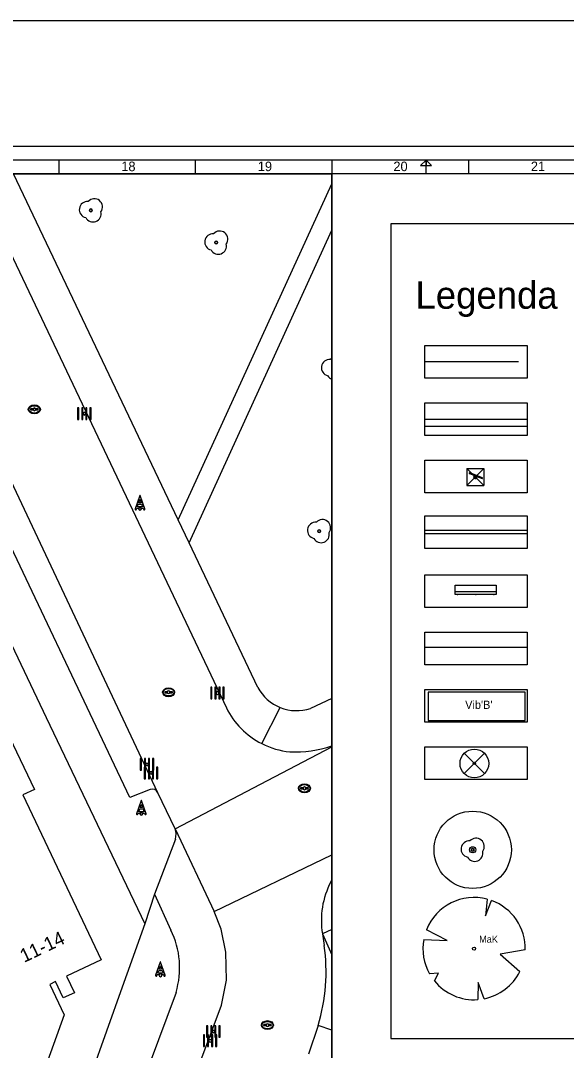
# Model space of a CAD drawing. Extents: x 192664 to 192925, y 446334 to 446521.
# Drawn here: x 192837.8 to 192877.8, y 446445.5 to 446521 of the extents above; entities that cross this region are included whole.
import ezdxf

# ---------------------------------------------------------------- set-up
doc = ezdxf.new("R2010")
doc.units = 0
for name, color, linetype in [('( Toegevoegd 29-11-2021 14_41_42) wegdeel vlak', 7, 'Continuous'), ('1010 viewport', 7, 'Continuous'), ('201011 legenda', 7, 'Continuous'), ('201020 hulplijnen', 7, 'Continuous'), ('205134 wortelgeleidingsscherm', 7, 'Continuous'), ('B-GV-GR-BOOM-S', 7, 'Continuous'), ('B-GV-KG-GRENS_WERKGRENS-G', 7, 'Continuous'), ('boom', 7, 'Continuous'), ('bovenleidingmast', 7, 'Continuous'), ('huisnummerreeks BGT', 7, 'Continuous'), ('inspectie-   rioolput', 7, 'Continuous'), ('kant open verharding', 7, 'Continuous'), ('kant verharding', 7, 'Continuous'), ('kolk', 7, 'Continuous'), ('N-GV-GR-BEPLANTING-G', 7, 'Continuous'), ('N-GV-GR-BOOM-S', 7, 'Continuous'), ('N-GV-IE-MEUBILAIR_WEGMEUBILAIR_ZITBANK-S', 7, 'Continuous'), ('N-GV-VH-VERHARDING_HALFVERHARDING-G', 7, 'Continuous'), ('pand op maaiveld vlak', 7, 'Continuous'), ('speelvoorziening', 7, 'Continuous'), ('TEKST', 7, 'Continuous'), ('V-GV-IE-MEUBILAIR_WEGMEUBILAIR_SPEELTOESTEL-G', 7, 'Continuous'), ('verkeerseiland - berm', 7, 'Continuous'), ('X-XX-AL-TEKENBLAD-S', 7, 'Continuous'), ('X-XX-AL-TEKENBLAD_KADER-G', 7, 'Continuous')]:
    doc.layers.add(name, color=color, linetype=linetype)

msp = doc.modelspace()

# ---------------------------------------------------------------- linework, layer by layer
at = {"layer": '( Toegevoegd 29-11-2021 14_41_42) wegdeel vlak'}
for p, q in [((192849.384, 446484.404), (192860.643, 446509.019)), ((192850.183, 446482.725), (192860.643, 446505.623)), ((192867.462, 446491.779), (192874.962, 446491.779))]:
    msp.add_line(p, q, dxfattribs=at)
at = {"layer": '1010 viewport'}
msp.add_lwpolyline([(192675.743, 446509.756), (192860.643, 446509.756), (192860.643, 446345.556), (192675.743, 446345.556)], close=True, dxfattribs=at)
at = {"layer": '201011 legenda'}
msp.add_line((192860.643, 446345.556), (192860.643, 446509.756), dxfattribs=at)
for points in [[(192867.462, 446497.179), (192874.962, 446497.179), (192874.962, 446494.779), (192867.462, 446494.779)], [(192867.462, 446492.979), (192874.962, 446492.979), (192874.962, 446490.579), (192867.462, 446490.579)], [(192867.462, 446488.779), (192874.962, 446488.779), (192874.962, 446486.379), (192867.462, 446486.379)], [(192867.462, 446484.702), (192874.962, 446484.702), (192874.962, 446482.302), (192867.462, 446482.302)], [(192867.462, 446480.379), (192874.962, 446480.379), (192874.962, 446477.979), (192867.462, 446477.979)], [(192867.462, 446476.179), (192874.962, 446476.179), (192874.962, 446473.779), (192867.462, 446473.779)], [(192867.462, 446471.979), (192874.962, 446471.979), (192874.962, 446469.579), (192867.462, 446469.579)], [(192867.462, 446467.779), (192874.962, 446467.779), (192874.962, 446465.379), (192867.462, 446465.379)]]:
    msp.add_lwpolyline(points, close=True, dxfattribs=at)
at = {"layer": '201020 hulplijnen'}
msp.add_lwpolyline([(192864.958, 446446.417), (192902.755, 446446.417), (192902.755, 446506.094), (192864.958, 446506.094)], close=True, dxfattribs=at)
at = {"layer": '205134 wortelgeleidingsscherm'}
msp.add_line((192867.462, 446475.064), (192874.962, 446475.064), dxfattribs=at)
at = {"layer": 'B-GV-GR-BOOM-S'}
for p, q in [((192871.852, 446467.325), (192870.317, 446465.79)), ((192871.852, 446465.79), (192870.317, 446467.325))]:
    msp.add_line(p, q, dxfattribs=at)
for centre, radius in [((192871.085, 446466.557), 1.05), ((192871.085, 446466.557), 0.084), ((192870.961, 446460.232), 2.832), ((192870.961, 446460.232), 0.227)]:
    msp.add_circle(centre, radius, dxfattribs=at)
at = {"layer": 'B-GV-KG-GRENS_WERKGRENS-G'}
msp.add_line((192874.314, 446495.979), (192867.462, 446495.979), dxfattribs=at)
at = {"layer": 'boom'}
for p, q in [((192860.643, 446495.55), (192860.643, 446496.247)), ((192860.643, 446495.45), (192860.643, 446495.55)), ((192860.643, 446494.699), (192860.643, 446495.45))]:
    msp.add_line(p, q, dxfattribs=at)
for centre in [(192842.997, 446507.076), (192852.18, 446504.71), (192859.71, 446483.574), (192870.961, 446460.232)]:
    msp.add_circle(centre, 0.1, dxfattribs=at)
for centre, radius, start, end in [((192842.747, 446507.126), 0.6, 85.13702, 257.75442), ((192843.247, 446507.326), 0.6, 323.54458, 138.4658), ((192843.147, 446506.826), 0.6, 208.50578, 13.83556), ((192842.997, 446507.076), 0.1, 0, 180), ((192842.997, 446507.076), 0.1, 180, 0), ((192851.93, 446504.76), 0.6, 85.13702, 257.75442), ((192852.43, 446504.96), 0.6, 323.54458, 138.4658), ((192852.33, 446504.46), 0.6, 208.50578, 13.83556), ((192852.18, 446504.71), 0.1, 0, 180), ((192852.18, 446504.71), 0.1, 180, 0), ((192860.48, 446495.55), 0.6, 85.13702, 257.75442), ((192860.98, 446495.75), 0.6, 124.12747, 138.4658), ((192860.73, 446495.5), 0.1, 150.02178, 209.97822), ((192860.73, 446495.5), 0.1, 150.02178, 209.97822), ((192860.88, 446495.25), 0.6, 208.50578, 246.77336), ((192859.46, 446483.624), 0.6, 85.13702, 257.75442), ((192859.96, 446483.824), 0.6, 323.54458, 138.4658), ((192859.86, 446483.324), 0.6, 208.50578, 13.83556), ((192859.71, 446483.574), 0.1, 0, 180), ((192859.71, 446483.574), 0.1, 180, 0), ((192870.711, 446460.282), 0.6, 85.13702, 257.75442), ((192871.211, 446460.482), 0.6, 323.54458, 138.4658), ((192871.111, 446459.982), 0.6, 208.50578, 13.83556), ((192870.961, 446460.232), 0.1, 0, 180), ((192870.961, 446460.232), 0.1, 180, 0)]:
    msp.add_arc(centre, radius, start, end, dxfattribs=at)
at = {"layer": 'bovenleidingmast'}
for p, q in [((192846.583, 446486.18), (192846.242, 446485.207)), ((192846.942, 446485.207), (192846.601, 446486.18)), ((192846.684, 446463.846), (192846.343, 446462.873)), ((192847.043, 446462.873), (192846.702, 446463.846)), ((192848.079, 446452.011), (192847.738, 446451.038)), ((192848.438, 446451.038), (192848.097, 446452.011))]:
    msp.add_line(p, q, dxfattribs=at)
for points in [[(192846.714, 446485.557), (192846.784, 446485.357), (192846.4, 446485.357), (192846.47, 446485.557)], [(192846.815, 446463.223), (192846.885, 446463.023), (192846.501, 446463.023), (192846.571, 446463.223)], [(192848.21, 446451.388), (192848.28, 446451.188), (192847.896, 446451.188), (192847.966, 446451.388)]]:
    msp.add_lwpolyline(points, close=True, dxfattribs=at)
for points in [[(192846.601, 446485.877), (192846.679, 446485.657), (192846.505, 446485.657), (192846.583, 446485.877)], [(192846.336, 446485.174), (192846.365, 446485.257), (192846.505, 446485.257)], [(192846.679, 446485.257), (192846.819, 446485.257), (192846.848, 446485.174)], [(192846.702, 446463.543), (192846.78, 446463.323), (192846.606, 446463.323), (192846.684, 446463.543)], [(192846.437, 446462.84), (192846.466, 446462.923), (192846.606, 446462.923)], [(192846.78, 446462.923), (192846.92, 446462.923), (192846.949, 446462.84)], [(192848.097, 446451.708), (192848.175, 446451.488), (192848.001, 446451.488), (192848.079, 446451.708)], [(192847.832, 446451.005), (192847.861, 446451.088), (192848.001, 446451.088)], [(192848.175, 446451.088), (192848.315, 446451.088), (192848.344, 446451.005)]]:
    msp.add_lwpolyline(points, dxfattribs=at)
for centre, radius, start, end in [((192846.592, 446486.177), 0.01, 19.29005, 160.70995), ((192846.592, 446485.874), 0.01, 19.29005, 160.70995), ((192846.289, 446485.19), 0.05, 160.70995, 340.70995), ((192846.592, 446485.207), 0.1, 0, 180), ((192846.592, 446485.207), 0.1, 180, 0), ((192846.592, 446485.207), 0.1, 30, 150), ((192846.895, 446485.19), 0.05, 199.29005, 19.29005), ((192846.693, 446463.843), 0.01, 19.29005, 160.70995), ((192846.693, 446463.54), 0.01, 19.29005, 160.70995), ((192846.39, 446462.856), 0.05, 160.70995, 340.70995), ((192846.693, 446462.873), 0.1, 0, 180), ((192846.693, 446462.873), 0.1, 180, 0), ((192846.693, 446462.873), 0.1, 30, 150), ((192846.996, 446462.856), 0.05, 199.29005, 19.29005), ((192848.088, 446452.008), 0.01, 19.29005, 160.70995), ((192848.088, 446451.705), 0.01, 19.29005, 160.70995), ((192847.785, 446451.021), 0.05, 160.70995, 340.70995), ((192848.088, 446451.038), 0.1, 0, 180), ((192848.088, 446451.038), 0.1, 180, 0), ((192848.088, 446451.038), 0.1, 30, 150), ((192848.391, 446451.021), 0.05, 199.29005, 19.29005)]:
    msp.add_arc(centre, radius, start, end, dxfattribs=at)
at = {"layer": 'inspectie-   rioolput'}
for p, q in [((192838.76, 446492.534), (192838.603, 446492.534)), ((192838.603, 446492.459), (192838.76, 446492.459)), ((192839.103, 446492.534), (192838.946, 446492.534)), ((192838.946, 446492.459), (192839.103, 446492.459)), ((192848.596, 446471.812), (192848.439, 446471.812)), ((192848.939, 446471.812), (192848.782, 446471.812)), ((192848.439, 446471.737), (192848.596, 446471.737)), ((192848.782, 446471.737), (192848.939, 446471.737)), ((192858.543, 446464.774), (192858.386, 446464.774)), ((192858.386, 446464.699), (192858.543, 446464.699)), ((192858.886, 446464.774), (192858.729, 446464.774)), ((192858.729, 446464.699), (192858.886, 446464.699)), ((192855.834, 446447.427), (192855.677, 446447.427)), ((192855.677, 446447.353), (192855.834, 446447.353)), ((192856.177, 446447.427), (192856.02, 446447.427)), ((192856.02, 446447.353), (192856.177, 446447.353))]:
    msp.add_line(p, q, dxfattribs=at)
for centre, radius, start, end in [((192838.603, 446492.496), 0.0375, 90, 270), ((192838.853, 446492.496), 0.1, 0, 180), ((192838.853, 446492.496), 0.1, 157.97569, 180), ((192838.853, 446492.496), 0.1, 180, 202.02431), ((192838.853, 446492.496), 0.1, 180, 0), ((192838.853, 446492.496), 0.1, 0, 22.02431), ((192838.853, 446492.496), 0.1, 337.97569, 0), ((192839.103, 446492.496), 0.0375, 270, 90), ((192848.439, 446471.775), 0.0375, 90, 270), ((192848.689, 446471.775), 0.1, 0, 180), ((192848.689, 446471.775), 0.1, 157.97569, 180), ((192848.689, 446471.775), 0.1, 180, 202.02431), ((192848.689, 446471.775), 0.1, 180, 0), ((192848.689, 446471.775), 0.1, 0, 22.02431), ((192848.689, 446471.775), 0.1, 337.97569, 0), ((192848.939, 446471.775), 0.0375, 270, 90), ((192858.386, 446464.737), 0.0375, 90, 270), ((192858.636, 446464.737), 0.1, 0, 180), ((192858.636, 446464.737), 0.1, 157.97569, 180), ((192858.636, 446464.737), 0.1, 180, 202.02431), ((192858.636, 446464.737), 0.1, 180, 0), ((192858.636, 446464.737), 0.1, 0, 22.02431), ((192858.636, 446464.737), 0.1, 337.97569, 0), ((192858.886, 446464.737), 0.0375, 270, 90), ((192855.677, 446447.39), 0.0375, 90, 270), ((192855.927, 446447.39), 0.1, 0, 180), ((192855.927, 446447.39), 0.1, 157.97569, 180), ((192855.927, 446447.39), 0.1, 180, 202.02431), ((192855.927, 446447.39), 0.1, 180, 0), ((192855.927, 446447.39), 0.1, 0, 22.02431), ((192855.927, 446447.39), 0.1, 337.97569, 0), ((192856.177, 446447.39), 0.0375, 270, 90)]:
    msp.add_arc(centre, radius, start, end, dxfattribs=at)
for centre, major_axis, ratio in [((192838.853, 446492.496), (-0.442, 0), 0.73911), ((192838.853, 446492.496), (-0.392, 0), 0.689655), ((192848.689, 446471.775), (-0.442, 0), 0.73911), ((192848.689, 446471.775), (-0.392, 0), 0.689655), ((192858.636, 446464.737), (-0.442, 0), 0.73911), ((192858.636, 446464.737), (-0.392, 0), 0.689655), ((192855.927, 446447.39), (-0.442, 0), 0.73911), ((192855.927, 446447.39), (-0.392, 0), 0.689655)]:
    msp.add_ellipse(centre, major_axis=major_axis, ratio=ratio, dxfattribs=at)
at = {"layer": 'kant open verharding'}
for p, q in [((192849.384, 446484.404), (192837.327, 446509.756)), ((192835.606, 446507.086), (192852.92, 446470.626)), ((192850.183, 446482.725), (192849.384, 446484.404)), ((192855.223, 446472.129), (192850.183, 446482.725)), ((192860.643, 446471.328), (192859.082, 446470.584)), ((192855.509, 446468.01), (192856.872, 446470.656)), ((192849.159, 446461.777), (192860.643, 446467.769)), ((192849.159, 446461.777), (192847.908, 446464.417)), ((192852.016, 446455.709), (192860.643, 446459.852)), ((192847.645, 446456.987), (192846.946, 446454.816)), ((192860.643, 446454.394), (192859.957, 446454.068)), ((192859.639, 446447.374), (192858.944, 446445.253))]:
    msp.add_line(p, q, dxfattribs=at)
for points in [[(192820.967, 446509.756), (192830.801, 446488.882), (192835.291, 446479.169), (192839.711, 446469.931), (192846.946, 446454.816)], [(192846.946, 446454.816), (192845.635, 446451.129), (192845.293, 446450.169), (192841.851, 446440.492), (192835.693, 446423.446), (192835.401, 446422.35)]]:
    msp.add_lwpolyline(points, dxfattribs=at)
for centre, radius, start, end in [((192858.074, 446473.662), 3.237, 208.25805, 248.19512), ((192858.147, 446473.21), 5.83, 206.30393, 243.10165), ((192858.076, 446473.668), 3.244, 248.20975, 288.05827), ((192858.148, 446473.204), 5.826, 243.06402, 264.2745), ((192857.92, 446475.928), 8.528, 267.62464, 288.62029)]:
    msp.add_arc(centre, radius, start, end, dxfattribs=at)
at = {"layer": 'kant verharding'}
for p, q in [((192847.908, 446464.417), (192829.185, 446504.028)), ((192849.159, 446461.777), (192852.016, 446455.709)), ((192849.185, 446461.016), (192847.645, 446456.987)), ((192847.645, 446456.987), (192848.853, 446454.346))]:
    msp.add_line(p, q, dxfattribs=at)
for points in [[(192847.34, 446464.645), (192845.844, 446464.076), (192824.376, 446509.29), (192825.458, 446509.756)], [(192849.014, 446439.367), (192852.558, 446448.85), (192852.92, 446450.686), (192852.89, 446452.743), (192852.529, 446454.425), (192852.02, 446455.701), (192852.016, 446455.709)], [(192849.233, 446449.789), (192845.968, 446441.003), (192848.719, 446439.99)]]:
    msp.add_lwpolyline(points, dxfattribs=at)
for centre, radius, start, end in [((192847.501, 446464.224), 0.451, 25.37972, 110.87839), ((192848.036, 446461.358), 1.199, 343.44366, 20.4699), ((192865.975, 446455.055), 6.099, 152.41348, 189.31098), ((192867.606, 446454.896), 7.643, 155.65213, 157.02281), ((192843.293, 446451.588), 6.206, 343.14873, 26.3848)]:
    msp.add_arc(centre, radius, start, end, dxfattribs=at)
at = {"layer": 'kolk'}
for points in [[(192842.113, 446492.182), (192842.113, 446492.607), (192842.028, 446492.607), (192842.028, 446492.182), (192842.028, 446491.757), (192842.113, 446491.757)], [(192842.411, 446492.182), (192842.411, 446492.607), (192842.326, 446492.607), (192842.326, 446492.182), (192842.326, 446491.757), (192842.411, 446491.757)], [(192842.708, 446492.182), (192842.708, 446492.607), (192842.623, 446492.607), (192842.623, 446492.182), (192842.623, 446491.757), (192842.708, 446491.757)], [(192843.006, 446492.182), (192843.006, 446492.607), (192842.921, 446492.607), (192842.921, 446492.182), (192842.921, 446491.757), (192843.006, 446491.757)], [(192851.865, 446471.718), (192851.865, 446472.143), (192851.78, 446472.143), (192851.78, 446471.718), (192851.78, 446471.293), (192851.865, 446471.293)], [(192852.163, 446471.718), (192852.163, 446472.143), (192852.078, 446472.143), (192852.078, 446471.718), (192852.078, 446471.293), (192852.163, 446471.293)], [(192852.46, 446471.718), (192852.46, 446472.143), (192852.375, 446472.143), (192852.375, 446471.718), (192852.375, 446471.293), (192852.46, 446471.293)], [(192852.758, 446471.718), (192852.758, 446472.143), (192852.673, 446472.143), (192852.673, 446471.718), (192852.673, 446471.293), (192852.758, 446471.293)], [(192846.702, 446466.491), (192846.702, 446466.916), (192846.617, 446466.916), (192846.617, 446466.491), (192846.617, 446466.066), (192846.702, 446466.066)], [(192847, 446466.491), (192847, 446466.916), (192846.915, 446466.916), (192846.915, 446466.491), (192846.915, 446466.066), (192847, 446466.066)], [(192847.297, 446466.491), (192847.297, 446466.916), (192847.212, 446466.916), (192847.212, 446466.491), (192847.212, 446466.066), (192847.297, 446466.066)], [(192847.595, 446466.491), (192847.595, 446466.916), (192847.51, 446466.916), (192847.51, 446466.491), (192847.51, 446466.066), (192847.595, 446466.066)], [(192846.996, 446465.862), (192846.996, 446466.287), (192846.911, 446466.287), (192846.911, 446465.862), (192846.911, 446465.437), (192846.996, 446465.437)], [(192847.294, 446465.862), (192847.294, 446466.287), (192847.209, 446466.287), (192847.209, 446465.862), (192847.209, 446465.437), (192847.294, 446465.437)], [(192847.591, 446465.862), (192847.591, 446466.287), (192847.506, 446466.287), (192847.506, 446465.862), (192847.506, 446465.437), (192847.591, 446465.437)], [(192847.889, 446465.862), (192847.889, 446466.287), (192847.804, 446466.287), (192847.804, 446465.862), (192847.804, 446465.437), (192847.889, 446465.437)], [(192851.561, 446446.923), (192851.561, 446447.348), (192851.476, 446447.348), (192851.476, 446446.923), (192851.476, 446446.498), (192851.561, 446446.498)], [(192851.859, 446446.923), (192851.859, 446447.348), (192851.774, 446447.348), (192851.774, 446446.923), (192851.774, 446446.498), (192851.859, 446446.498)], [(192852.156, 446446.923), (192852.156, 446447.348), (192852.071, 446447.348), (192852.071, 446446.923), (192852.071, 446446.498), (192852.156, 446446.498)], [(192852.454, 446446.923), (192852.454, 446447.348), (192852.369, 446447.348), (192852.369, 446446.923), (192852.369, 446446.498), (192852.454, 446446.498)], [(192851.323, 446446.248), (192851.323, 446446.673), (192851.238, 446446.673), (192851.238, 446446.248), (192851.238, 446445.823), (192851.323, 446445.823)], [(192851.621, 446446.248), (192851.621, 446446.673), (192851.536, 446446.673), (192851.536, 446446.248), (192851.536, 446445.823), (192851.621, 446445.823)], [(192851.918, 446446.248), (192851.918, 446446.673), (192851.833, 446446.673), (192851.833, 446446.248), (192851.833, 446445.823), (192851.918, 446445.823)], [(192852.216, 446446.248), (192852.216, 446446.673), (192852.131, 446446.673), (192852.131, 446446.248), (192852.131, 446445.823), (192852.216, 446445.823)]]:
    msp.add_lwpolyline(points, close=True, dxfattribs=at)
for centre, start, end in [((192842.517, 446492.182), 0, 180), ((192842.517, 446492.182), 180, 0), ((192852.269, 446471.718), 0, 180), ((192852.269, 446471.718), 180, 0), ((192847.106, 446466.491), 0, 180), ((192847.106, 446466.491), 180, 0), ((192847.4, 446465.862), 0, 180), ((192847.4, 446465.862), 180, 0), ((192851.965, 446446.923), 0, 180), ((192851.965, 446446.923), 180, 0), ((192851.727, 446446.248), 0, 180), ((192851.727, 446446.248), 180, 0)]:
    msp.add_arc(centre, 0.1, start, end, dxfattribs=at)
at = {"layer": 'N-GV-GR-BEPLANTING-G'}
msp.add_lwpolyline([(192867.689, 446469.713), (192874.799, 446469.713), (192874.799, 446471.791), (192867.689, 446471.791)], close=True, dxfattribs=at)
at = {"layer": 'N-GV-GR-BOOM-S'}
for points in [[(192872.021, 446456.62), (192871.91, 446455.384), (192872.35, 446456.517)], [(192867.374, 446453.663), (192869.104, 446453.581), (192867.579, 446454.382)], [(192874.809, 446452.9), (192872.97, 446452.587), (192874.408, 446451.306)], [(192868.16, 446450.624), (192868.455, 446451.196), (192867.798, 446451.154)], [(192871.801, 446449.321), (192871.374, 446450.517), (192871.331, 446449.257)]]:
    msp.add_lwpolyline(points, dxfattribs=at)
msp.add_circle((192871.062, 446452.996), 0.112, dxfattribs=at)
for start, end in [(75.18441, 158.29895), (358.52408, 69.90661), (169.74905, 209.43023), (219.26669, 274.10684), (281.36007, 333.20465)]:
    msp.add_arc((192871.062, 446452.996), 3.748, start, end, dxfattribs=at)
at = {"layer": 'N-GV-IE-MEUBILAIR_WEGMEUBILAIR_ZITBANK-S'}
msp.add_line((192872.684, 446479.131), (192869.684, 446479.126), dxfattribs=at)
msp.add_lwpolyline([(192872.683, 446479.621), (192872.685, 446478.942), (192869.685, 446478.936), (192869.683, 446479.616)], close=True, dxfattribs=at)
for points in [[(192869.885, 446478.937), (192869.885, 446478.902), (192869.834, 446478.901), (192869.834, 446478.937)], [(192871.21, 446478.939), (192871.21, 446478.904), (192871.159, 446478.904), (192871.159, 446478.939)], [(192872.535, 446478.941), (192872.535, 446478.906), (192872.485, 446478.906), (192872.485, 446478.941)]]:
    msp.add_lwpolyline(points, dxfattribs=at)
at = {"layer": 'N-GV-VH-VERHARDING_HALFVERHARDING-G'}
msp.add_lwpolyline([(192867.462, 446483.637), (192874.962, 446483.637), (192874.962, 446483.366), (192867.462, 446483.366)], close=True, dxfattribs=at)
at = {"layer": 'pand op maaiveld vlak'}
msp.add_line((192867.462, 446491.257), (192874.962, 446491.257), dxfattribs=at)
msp.add_lwpolyline([(192836.54, 446469.53), (192836.973, 446468.62), (192837.036, 446468.487), (192838.86, 446464.658), (192838.011, 446464.254), (192843.76, 446452.181), (192841.215, 446450.969), (192841.788, 446449.766), (192840.974, 446449.379), (192840.403, 446450.578), (192839.983, 446450.377), (192841.046, 446448.145), (192838.693, 446441.612)], dxfattribs=at)
at = {"layer": 'speelvoorziening'}
for p, q in [((192870.727, 446487.787), (192871.089, 446487.647)), ((192871.67, 446487.485), (192870.748, 446487.842)), ((192871.269, 446487.577), (192871.648, 446487.43))]:
    msp.add_line(p, q, dxfattribs=at)
msp.add_circle((192871.154, 446487.547), 0.1, dxfattribs=at)
for centre, radius, start, end in [((192870.737, 446487.814), 0.0297, 68.83874, 248.83874), ((192871.154, 446487.547), 0.119, 123.04996, 14.62752), ((192871.154, 446487.547), 0.1, 0, 180), ((192871.154, 446487.547), 0.1, 180, 0), ((192871.659, 446487.458), 0.0297, 248.83874, 68.83874)]:
    msp.add_arc(centre, radius, start, end, dxfattribs=at)
at = {"layer": 'V-GV-IE-MEUBILAIR_WEGMEUBILAIR_SPEELTOESTEL-G'}
for p, q in [((192870.529, 446488.172), (192870.529, 446486.922)), ((192870.529, 446488.172), (192871.779, 446488.172)), ((192870.529, 446488.172), (192871.779, 446486.922)), ((192870.529, 446486.922), (192871.779, 446488.172)), ((192871.779, 446488.172), (192871.779, 446486.922)), ((192870.529, 446486.922), (192871.779, 446486.922))]:
    msp.add_line(p, q, dxfattribs=at)
at = {"layer": 'verkeerseiland - berm'}
for p, q in [((192859.957, 446454.068), (192860.643, 446452.54)), ((192859.957, 446454.068), (192860.085, 446453.225)), ((192860.643, 446447.016), (192859.639, 446447.374))]:
    msp.add_line(p, q, dxfattribs=at)
msp.add_arc((192846.65, 446451.307), 13.572, 343.15593, 8.12604, dxfattribs=at)
at = {"layer": 'X-XX-AL-TEKENBLAD-S'}
for p, q in [((192909.543, 446511.756), (192671.743, 446511.756)), ((192908.543, 446510.756), (192674.743, 446510.756)), ((192840.643, 446510.756), (192840.643, 446509.756)), ((192850.643, 446510.756), (192850.643, 446509.756)), ((192860.643, 446510.756), (192860.643, 446509.756)), ((192867.543, 446509.756), (192867.543, 446510.756)), ((192870.643, 446510.756), (192870.643, 446509.756))]:
    msp.add_line(p, q, dxfattribs=at)
for points in [[(192867.543, 446510.356), (192867.543, 446510.756), (192867.143, 446510.356), (192867.543, 446510.356)], [(192867.543, 446510.756), (192867.543, 446510.356), (192867.943, 446510.356), (192867.543, 446510.756)]]:
    msp.add_lwpolyline(points, dxfattribs=at)
msp.add_lwpolyline([(192675.743, 446345.556), (192907.543, 446345.556), (192907.543, 446509.756), (192675.743, 446509.756)], close=True, dxfattribs=at)
at = {"layer": 'X-XX-AL-TEKENBLAD_KADER-G'}
msp.add_lwpolyline([(192664.22, 446520.974), (192925.029, 446520.974), (192925.029, 446333.894), (192664.22, 446333.894)], close=True, dxfattribs=at)

# ---------------------------------------------------------------- texts
at = {"layer": '201011 legenda'}
msp.add_text('Legenda', height=2, dxfattribs=at).set_placement((192866.773, 446499.865))
at = {"layer": 'huisnummerreeks BGT'}
msp.add_text('11-14', height=1, rotation=25.4, dxfattribs=at).set_placement((192838.098, 446451.943))
at = {"layer": 'TEKST'}
for s, height, p in [("Vib'B'", 0.6, (192870.41, 446470.555)), ('MaK', 0.5, (192871.433, 446453.434))]:
    msp.add_text(s, height=height, dxfattribs=at).set_placement(p)
at = {"layer": 'X-XX-AL-TEKENBLAD-S'}
for s, p in [('18', (192845.224, 446509.945)), ('19', (192855.224, 446509.945)), ('20', (192865.154, 446509.945)), ('21', (192875.224, 446509.945))]:
    msp.add_text(s, height=0.7, dxfattribs=at).set_placement(p)

doc.saveas('drawing.dxf')
